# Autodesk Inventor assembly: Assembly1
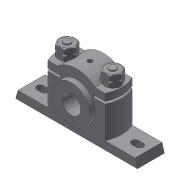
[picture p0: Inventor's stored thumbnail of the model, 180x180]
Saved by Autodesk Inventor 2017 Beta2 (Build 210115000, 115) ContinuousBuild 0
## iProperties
Created: 2016-03
Part Number: Assembly1
Document SubType Name: Assembly
Designer: Sandeep
Author: Sandeep
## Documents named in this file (7)
- C:\Inventor_2017\c09\Plumber block\Assembly1.iam
- C:\Inventor_2017\c09\Plumber block\Casting.ipt
- C:\Inventor_2017\c09\Plumber block\Brasses.ipt
- C:\Inventor_2017\c09\Plumber block\Cap.ipt
- C:\Inventor_2017\c09\Plumber block\Bolt.ipt
- C:\Inventor_2017\c09\Plumber block\Nut.ipt
- C:\Inventor_2017\c09\Plumber block\Lock Nut.ipt
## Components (9 placed, 6 different names)
1. Casting:1 — Mate:1, Mate:2, Insert:1, Insert:2, Angle:1, Angle:2
2. Brasses:1 — Mate:1, Mate:2, Mate:3, Mate:4
3. Cap:1 — Mate:3, Mate:4, Insert:3, Insert:5
4. Bolt:1 — Insert:1, Angle:1
5. Bolt:2 — Insert:2, Angle:2
6. Nut:1 — Insert:3, Insert:4
7. Nut:2 — Insert:5, Insert:6
8. Lock Nut:1 — Insert:4
9. Lock Nut:2 — Insert:6
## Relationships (12: Insert 6, Mate 4, Angle 2)
- Mate:1: Casting:1 ↔ Brasses:1
- Mate:2: Casting:1 ↔ Brasses:1
- Mate:3: Brasses:1 ↔ Cap:1
- Mate:4: Brasses:1 ↔ Cap:1
- Insert:1: Casting:1 ↔ Bolt:1
- Insert:2: Casting:1 ↔ Bolt:2
- Angle:1: Casting:1 ↔ Bolt:1
- Angle:2: Casting:1 ↔ Bolt:2
- Insert:3: Cap:1 ↔ Nut:1
- Insert:4: Nut:1 ↔ Lock Nut:1
- Insert:5: Cap:1 ↔ Nut:2
- Insert:6: Nut:2 ↔ Lock Nut:2
